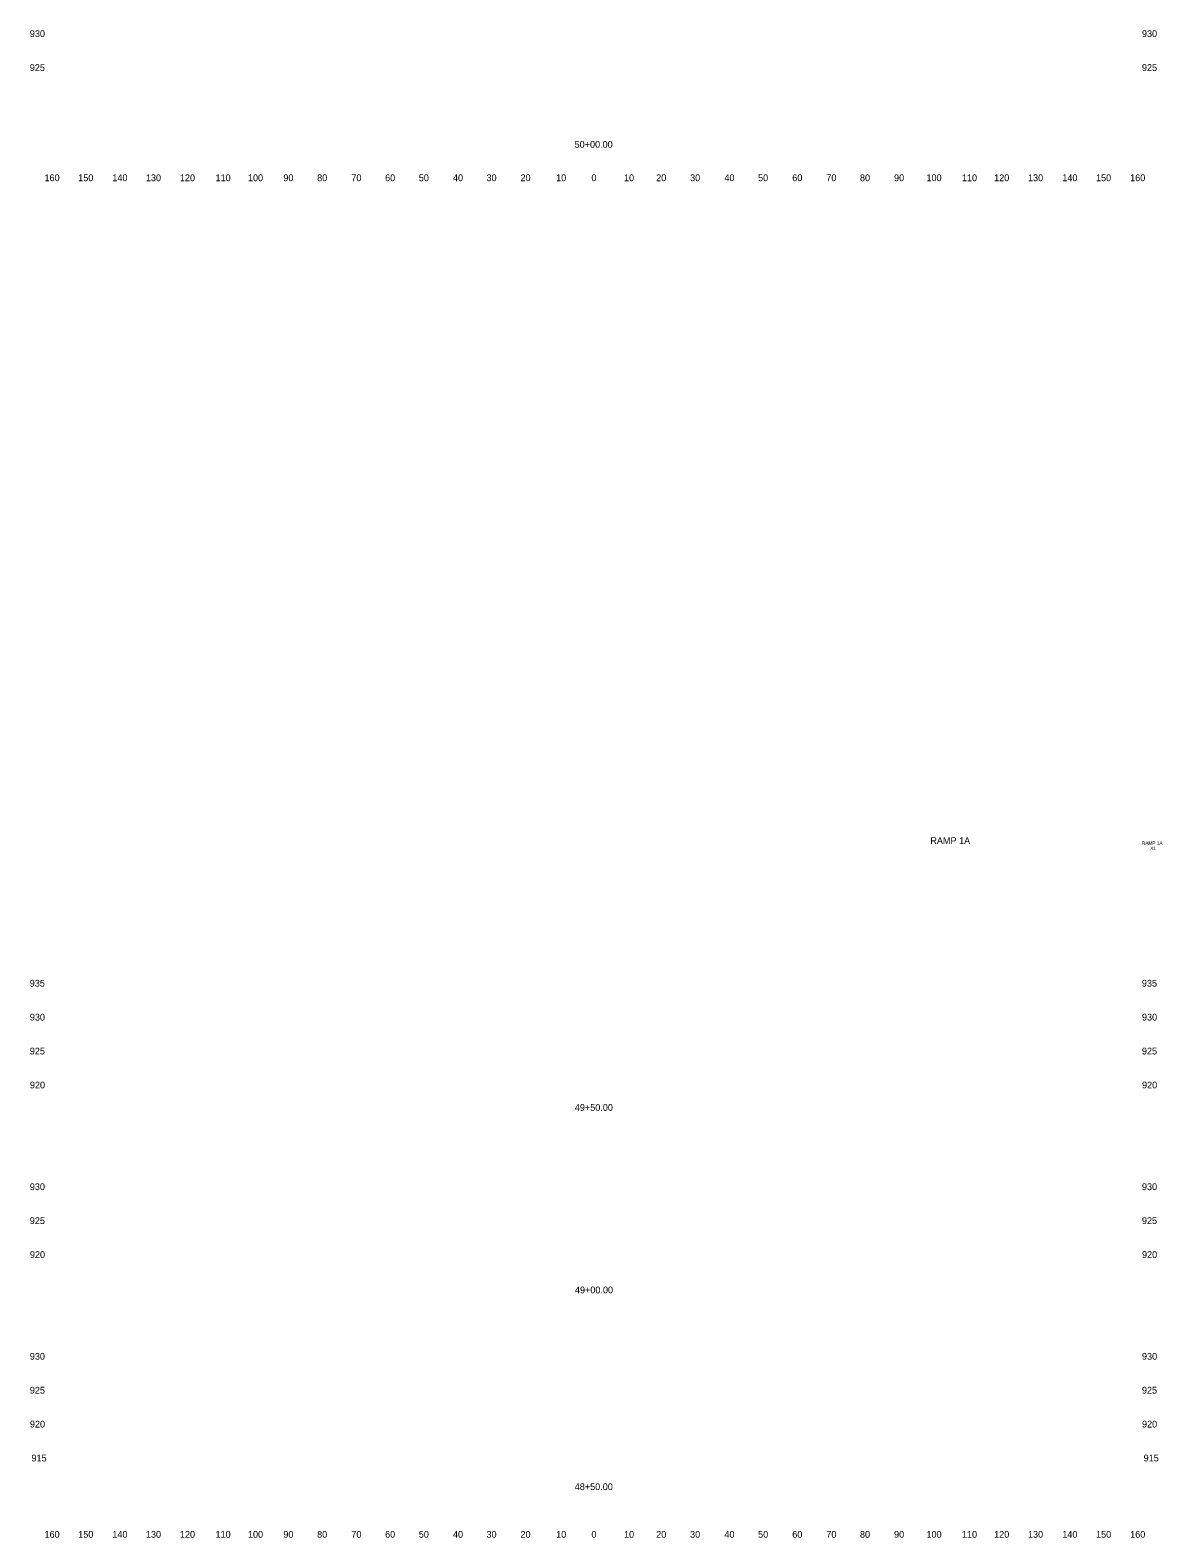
# Model space of a CAD drawing. Extents: x 4994 to 6873, y 4997 to 8804.
# Drawn here: x 4993.9 to 5327.4, y 4997.5 to 5442 of the extents above; entities that cross this region are included whole.
import ezdxf

# ---------------------------------------------------------------- set-up
doc = ezdxf.new("R2010")
doc.units = 0
for name, color, linetype in [('RD_SHT_ID', 7, 'Continuous'), ('RD_XS_TX_Offset', 7, 'Continuous'), ('RD_XS_TX_Station', 7, 'Continuous')]:
    doc.layers.add(name, color=color, linetype=linetype)

msp = doc.modelspace()

# ---------------------------------------------------------------- texts
at = {"layer": 'RD_SHT_ID'}
for s, height, p in [('RAMP 1A', 2, (5259.21, 5202.06)), ('RAMP 1A', 1, (5321.57, 5201.8)), ('X1', 1, (5324.02, 5200.3))]:
    msp.add_text(s, height=height, dxfattribs=at).set_placement(p)
at = {"layer": 'RD_XS_TX_Offset'}
for s, p in [('930', (4993.78, 5440)), ('930', (5321.58, 5440)), ('925', (4993.77, 5430)), ('925', (5321.57, 5430)), ('160', (4998.1, 5397.5)), ('150', (5008.04, 5397.5)), ('140', (5018.1, 5397.5)), ('130', (5027.99, 5397.5)), ('120', (5038.01, 5397.5)), ('110', (5048.51, 5397.5)), ('100', (5058.07, 5397.5)), ('90', (5068.5, 5397.5)), ('80', (5078.46, 5397.5)), ('70', (5088.54, 5397.5)), ('60', (5098.5, 5397.5)), ('50', (5108.43, 5397.5)), ('40', (5118.5, 5397.5)), ('30', (5128.39, 5397.5)), ('20', (5138.4, 5397.5)), ('10', (5148.91, 5397.5)), ('0', (5159.3, 5397.5)), ('0', (5159.3, 5397.5)), ('10', (5168.91, 5397.5)), ('20', (5178.4, 5397.5)), ('30', (5188.39, 5397.5)), ('40', (5198.5, 5397.5)), ('50', (5208.43, 5397.5)), ('60', (5218.5, 5397.5)), ('70', (5228.54, 5397.5)), ('80', (5238.46, 5397.5)), ('90', (5248.5, 5397.5)), ('100', (5258.07, 5397.5)), ('110', (5268.51, 5397.5)), ('120', (5278.01, 5397.5)), ('130', (5287.99, 5397.5)), ('140', (5298.1, 5397.5)), ('150', (5308.04, 5397.5)), ('160', (5318.1, 5397.5)), ('935', (4993.75, 5160)), ('935', (5321.55, 5160)), ('930', (4993.78, 5150)), ('930', (5321.58, 5150)), ('925', (4993.77, 5140)), ('925', (5321.57, 5140)), ('920', (4993.8, 5130)), ('920', (5321.6, 5130)), ('930', (4993.78, 5100)), ('930', (5321.58, 5100)), ('925', (4993.77, 5090)), ('925', (5321.57, 5090)), ('920', (4993.8, 5080)), ('920', (5321.6, 5080)), ('930', (4993.78, 5050)), ('930', (5321.58, 5050)), ('925', (4993.77, 5040)), ('925', (5321.57, 5040)), ('920', (4993.8, 5030)), ('920', (5321.6, 5030)), ('915', (4994.27, 5020)), ('915', (5322.07, 5020)), ('160', (4998.1, 4997.5)), ('150', (5008.04, 4997.5)), ('140', (5018.1, 4997.5)), ('130', (5027.99, 4997.5)), ('120', (5038.01, 4997.5)), ('110', (5048.51, 4997.5)), ('100', (5058.07, 4997.5)), ('90', (5068.5, 4997.5)), ('80', (5078.46, 4997.5)), ('70', (5088.54, 4997.5)), ('60', (5098.5, 4997.5)), ('50', (5108.43, 4997.5)), ('40', (5118.5, 4997.5)), ('30', (5128.39, 4997.5)), ('20', (5138.4, 4997.5)), ('10', (5148.91, 4997.5)), ('0', (5159.3, 4997.5)), ('0', (5159.3, 4997.5)), ('10', (5168.91, 4997.5)), ('20', (5178.4, 4997.5)), ('30', (5188.39, 4997.5)), ('40', (5198.5, 4997.5)), ('50', (5208.43, 4997.5)), ('60', (5218.5, 4997.5)), ('70', (5228.54, 4997.5)), ('80', (5238.46, 4997.5)), ('90', (5248.5, 4997.5)), ('100', (5258.07, 4997.5)), ('110', (5268.51, 4997.5)), ('120', (5278.01, 4997.5)), ('130', (5287.99, 4997.5)), ('140', (5298.1, 4997.5)), ('150', (5308.04, 4997.5)), ('160', (5318.1, 4997.5))]:
    msp.add_text(s, height=2, dxfattribs=at).set_placement(p)
at = {"layer": 'RD_XS_TX_Station'}
for s, p in [('50+00.00', (5154.35, 5407.34)), ('49+50.00', (5154.42, 5123.37)), ('49+00.00', (5154.45, 5069.57)), ('48+50.00', (5154.39, 5011.55))]:
    msp.add_text(s, height=2, dxfattribs=at).set_placement(p)

doc.saveas('drawing.dxf')
